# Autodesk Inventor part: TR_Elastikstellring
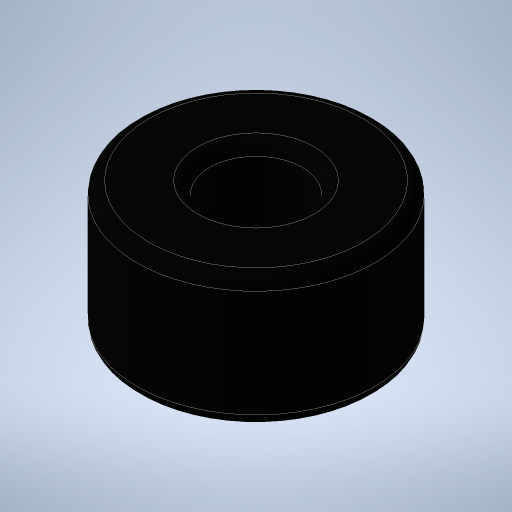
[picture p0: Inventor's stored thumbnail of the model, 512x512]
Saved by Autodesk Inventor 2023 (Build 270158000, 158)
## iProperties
Created: 2023-11
Part Number: TR_Elastikstellring
Material: Gummi
Document SubType Name: Modeling
Designer: Admin
Density: 0.93 g/cm^3
Appearance: Gummi - Schwarz
Author: Admin
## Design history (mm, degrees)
sketch "Skizze1"
  geometry: C1 r 1.95 at (0, 0); C2 r 5 at (0, 0); 1 further point
  constraints: 2 centre point, 2 coincident
  dimensions: "d0" = 3.9 diameter of C1; "d1" = 10 diameter of C2
extrude "Extrusion1" new body sketch "Skizze1" distance "d2" = 5.5; taper "d3" = 0 deg
fillet "Rundung1" dims "d4" = 0.5
node "Volumenkörper1"
